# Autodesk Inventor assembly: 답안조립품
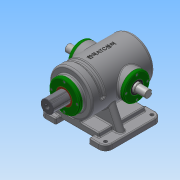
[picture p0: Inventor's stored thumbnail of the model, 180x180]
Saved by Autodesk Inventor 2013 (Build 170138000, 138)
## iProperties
Created: 2018-06
Part Number: 답안조립품
Document SubType Name: Assembly
Designer: Administrator
Mass: 8420.74 g
Surface Area: 4294.68 cm^2
Volume: 2307.06 cm^3
Density: 3.64998 g/cm^3
Author: Administrator
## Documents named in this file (13)
- C:\Users\Administrator\Desktop\380628V1016\답안조립품.iam
- C:\Users\Administrator\Desktop\380628V1016\본체.ipt
- C:\Users\Administrator\Desktop\380628V1016\베어링 6205.ipt
- 베어링 6205.ipt
- C:\Users\Administrator\Desktop\380628V1016\볼트 M4.ipt
- C:\Users\Administrator\Desktop\380628V1016\부시.ipt
- C:\Users\Administrator\Desktop\380628V1016\가변스프링.ipt
- C:\Users\Administrator\Desktop\380628V1016\슬라이드 커버.ipt
- C:\Users\Administrator\Desktop\380628V1016\슬라이드.ipt
- C:\Users\Administrator\Desktop\380628V1016\오일실.ipt
- 오일실.ipt
- C:\Users\Administrator\Desktop\380628V1016\축 커버.ipt
- C:\Users\Administrator\Desktop\380628V1016\편심축.ipt
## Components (1 placed, 1 different names)
1. 가변스프링:1
